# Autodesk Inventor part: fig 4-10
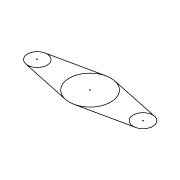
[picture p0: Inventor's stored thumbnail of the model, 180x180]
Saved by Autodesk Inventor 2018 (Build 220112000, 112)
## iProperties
Created: 2005-02
Part Number: fig 4-10
Document SubType Name: Modeling
Designer: CADCIM
Manufacturer: Standard
Standards Organization: Custom
Density: 1 g/cm^3
Material: Generic
Appearance: Default
Author: CADCIM
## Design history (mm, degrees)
sketch "Sketch1"
  geometry: L1 (-33.874, 5.844)-(-2.722, 12.469); L2 (2.595, 12.472)-(33.871, 5.852); L3 (-33.884, -5.902)-(-2.745, -12.585); L4 (2.595, -12.592)-(33.871, -5.972); A1 r 12.81 centre (-0.057, -0.06) between (-2.722, 12.469) and (2.595, 12.472); A2 r 6.006 centre (-32.624, -0.03) between (-33.874, 5.844) and (-33.884, -5.902); A3 r 6.043 centre (32.619, -0.06) between (33.871, 5.852) and (33.871, -5.972)
  constraints: 8 end point, 8 point on circle, 8 tangent, 3 centre point, 1 other
